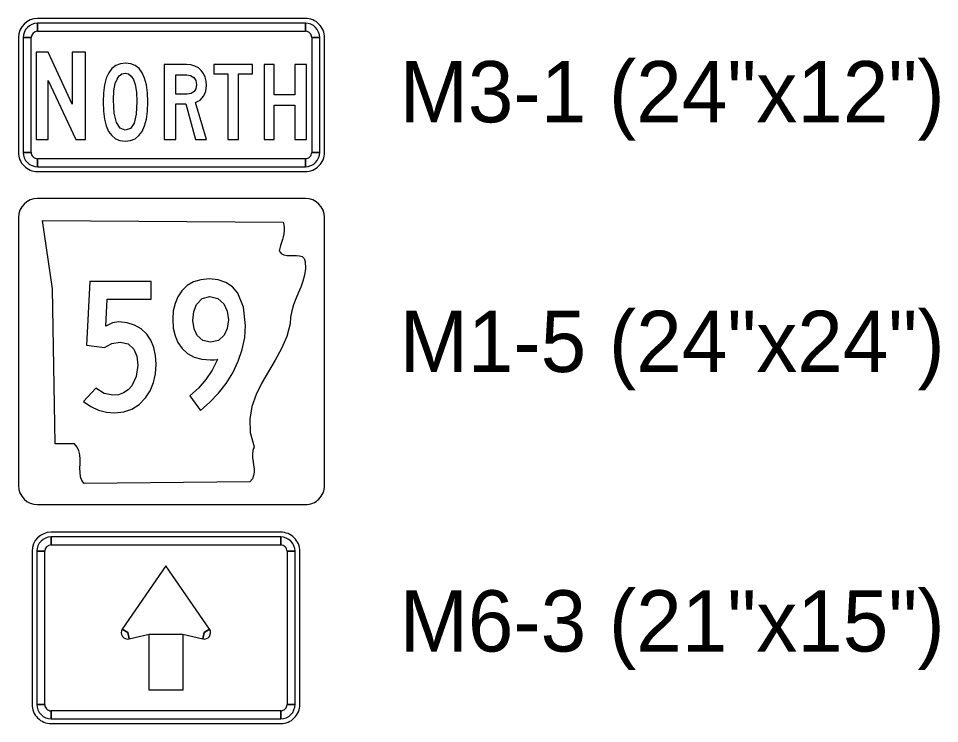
# Model space of a CAD drawing. Extents: x 620864 to 620948.6, y 415499.7 to 415559.1.
# Drawn here: x 620910.53 to 620916.55, y 415510.88 to 415515.48 of the extents above; entities that cross this region are included whole.
import ezdxf

# ---------------------------------------------------------------- set-up
doc = ezdxf.new("R2010")
doc.units = 0
doc.layers.add('SIGNS', color=7, linetype='Continuous')

msp = doc.modelspace()

# ---------------------------------------------------------------- linework, layer by layer
at = {"layer": 'SIGNS'}
for p, q in [((620912.4076, 415515.4826), (620910.6576, 415515.4826)), ((620910.6576, 415515.3993), (620910.6576, 415515.4514)), ((620912.4076, 415515.4514), (620912.4076, 415515.3993)), ((620910.5326, 415515.3576), (620910.5326, 415514.6076)), ((620910.5639, 415515.3576), (620910.616, 415515.3576)), ((620912.4493, 415515.3576), (620912.5014, 415515.3576)), ((620912.5326, 415514.6076), (620912.5326, 415515.3576)), ((620910.616, 415514.6076), (620910.5639, 415514.6076)), ((620912.5014, 415514.6076), (620912.4493, 415514.6076)), ((620910.6576, 415514.5139), (620910.6576, 415514.566)), ((620912.4076, 415514.566), (620912.4076, 415514.5139)), ((620910.6576, 415514.4826), (620912.4076, 415514.4826)), ((620912.4076, 415514.307), (620910.6576, 415514.307)), ((620910.5326, 415514.182), (620910.5326, 415512.432)), ((620912.5326, 415512.432), (620912.5326, 415514.182)), ((620910.5326, 415512.432), (620910.5326, 415512.432)), ((620910.6576, 415512.307), (620912.4076, 415512.307)), ((620912.2465, 415512.1272), (620910.7465, 415512.1272)), ((620910.7465, 415512.0438), (620910.7465, 415512.0959)), ((620912.2465, 415512.0959), (620912.2465, 415512.0438)), ((620910.6215, 415512.0022), (620910.6215, 415511.0022)), ((620910.6528, 415512.0022), (620910.7049, 415512.0022)), ((620912.2882, 415512.0022), (620912.3403, 415512.0022)), ((620912.3715, 415511.0022), (620912.3715, 415512.0022)), ((620911.2465, 415511.4709), (620911.2113, 415511.4932)), ((620911.2559, 415511.4303), (620911.2465, 415511.4709)), ((620911.7465, 415511.4709), (620911.7372, 415511.4303)), ((620911.7818, 415511.4932), (620911.7465, 415511.4709)), ((620910.7049, 415511.0022), (620910.6528, 415511.0022)), ((620912.3403, 415511.0022), (620912.2882, 415511.0022)), ((620910.7465, 415510.9084), (620910.7465, 415510.9605)), ((620912.2465, 415510.9605), (620912.2465, 415510.9084)), ((620910.7465, 415510.8772), (620912.2465, 415510.8772))]:
    msp.add_line(p, q, dxfattribs=at)
for points in [[(620912.4076, 415515.4514), (620910.6576, 415515.4514), (620910.6576, 415515.3993), (620912.4076, 415515.3993), (620912.4076, 415515.4514), (620912.4076, 415515.4514)], [(620910.5639, 415515.3576), (620910.5639, 415514.6076), (620910.616, 415514.6076), (620910.616, 415515.3576), (620910.5639, 415515.3576), (620910.5639, 415515.3576)], [(620912.5014, 415514.6076), (620912.5014, 415515.3576), (620912.4493, 415515.3576), (620912.4493, 415514.6076), (620912.5014, 415514.6076), (620912.5014, 415514.6076)], [(620910.648, 415514.691), (620910.7264, 415514.691), (620910.7264, 415515.0774), (620910.907, 415514.691), (620910.971, 415514.691), (620910.971, 415515.263), (620910.8835, 415515.263), (620910.8835, 415514.9217), (620910.7264, 415515.263), (620910.648, 415515.263)], [(620911.8998, 415514.691), (620911.971, 415514.691), (620911.971, 415515.1197), (620912.0625, 415515.1197), (620912.0625, 415515.1813), (620911.8103, 415515.1813), (620911.8103, 415515.1197), (620911.8998, 415515.1197)], [(620912.1373, 415514.691), (620912.2045, 415514.691), (620912.2045, 415514.916), (620912.3392, 415514.916), (620912.3392, 415514.691), (620912.4141, 415514.691), (620912.4141, 415515.1813), (620912.3392, 415515.1813), (620912.3392, 415514.9847), (620912.2045, 415514.9847), (620912.2045, 415515.1813), (620912.1373, 415515.1813)], [(620910.6576, 415514.5139), (620912.4076, 415514.5139), (620912.4076, 415514.566), (620910.6576, 415514.566), (620910.6576, 415514.5139), (620910.6576, 415514.5139)], [(620912.2625, 415514.1526), (620912.2672, 415514.1335), (620912.2689, 415514.1141), (620912.2682, 415514.0949), (620912.2659, 415514.0759), (620912.2619, 415514.0568), (620912.2572, 415514.0381), (620912.2515, 415514.019), (620912.2458, 415514.0006), (620912.2405, 415513.9823), (620912.2355, 415513.9639), (620912.2495, 415513.9477), (620912.2669, 415513.9386), (620912.2866, 415513.9345), (620912.308, 415513.9342), (620912.3293, 415513.9349), (620912.3501, 415513.9353), (620912.3691, 415513.9331), (620912.3858, 415513.9268), (620912.3989, 415513.9147), (620912.4069, 415513.8945), (620912.4076, 415513.849), (620912.4019, 415513.8064), (620912.3912, 415513.766), (620912.3768, 415513.7275), (620912.3611, 415513.6893), (620912.345, 415513.6515), (620912.33, 415513.6129), (620912.318, 415513.5733), (620912.3097, 415513.5318), (620912.3077, 415513.4878), (620912.2856, 415513.4055), (620912.2518, 415513.3273), (620912.211, 415513.2517), (620912.1669, 415513.1768), (620912.1238, 415513.1023), (620912.0861, 415513.0263), (620912.058, 415512.9477), (620912.0436, 415512.8651), (620912.047, 415512.7778), (620912.0727, 415512.6841), (620912.065, 415512.661), (620912.0624, 415512.6372), (620912.063, 415512.6133), (620912.066, 415512.5891), (620912.0694, 415512.5652), (620912.072, 415512.5417), (620912.0727, 415512.5186), (620912.0694, 415512.4969), (620912.061, 415512.4756), (620912.0456, 415512.4558), (620910.9619, 415512.4459), (620910.9472, 415512.4657), (620910.9389, 415512.4896), (620910.9352, 415512.516), (620910.9349, 415512.5443), (620910.9355, 415512.574), (620910.9359, 415512.6034), (620910.9339, 415512.6324), (620910.9282, 415512.6592), (620910.9171, 415512.6834), (620910.8988, 415512.704), (620910.7725, 415512.704), (620910.7544, 415513.7157), (620910.6909, 415514.1625), (620912.2625, 415514.1526), (620912.2625, 415514.1526)], [(620910.9575, 415512.981), (620911.0051, 415512.948), (620911.0551, 415512.9247), (620911.1073, 415512.9109), (620911.162, 415512.9063), (620911.2213, 415512.9122), (620911.2744, 415512.9304), (620911.3214, 415512.9609), (620911.3623, 415513.0039), (620911.393, 415513.0514), (620911.4149, 415513.104), (620911.4281, 415513.1615), (620911.4327, 415513.2245), (620911.4289, 415513.2819), (620911.4172, 415513.3341), (620911.3979, 415513.3802), (620911.3708, 415513.4207), (620911.3342, 415513.4553), (620911.2919, 415513.4802), (620911.2429, 415513.4952), (620911.1883, 415513.5003), (620911.147, 415513.4936), (620911.1034, 415513.4735), (620911.1126, 415513.6489), (620911.3997, 415513.6489), (620911.3997, 415513.7645), (620910.999, 415513.7645), (620910.9785, 415513.3485), (620911.0949, 415513.3335), (620911.1439, 415513.3595), (620911.1968, 415513.3683), (620911.2489, 415513.3565), (620911.2868, 415513.3217), (620911.3064, 415513.2757), (620911.3131, 415513.2187), (620911.303, 415513.144), (620911.2731, 415513.0828), (620911.2486, 415513.0558), (620911.2199, 415513.0369), (620911.1867, 415513.0253), (620911.1493, 415513.0217), (620911.092, 415513.0334), (620911.0382, 415513.0687)], [(620912.2465, 415512.0959), (620910.7465, 415512.0959), (620910.7465, 415512.0438), (620912.2465, 415512.0438), (620912.2465, 415512.0959), (620912.2465, 415512.0959)], [(620910.6528, 415512.0022), (620910.6528, 415511.0022), (620910.7049, 415511.0022), (620910.7049, 415512.0022), (620910.6528, 415512.0022), (620910.6528, 415512.0022)], [(620912.3403, 415511.0022), (620912.3403, 415512.0022), (620912.2882, 415512.0022), (620912.2882, 415511.0022), (620912.3403, 415511.0022), (620912.3403, 415511.0022)], [(620911.4965, 415511.9084), (620911.2113, 415511.4932), (620911.2465, 415511.4709), (620911.2559, 415511.4303), (620911.3872, 415511.4605), (620911.6059, 415511.4605), (620911.7372, 415511.4303), (620911.7465, 415511.4709), (620911.7818, 415511.4932), (620911.4965, 415511.9084), (620911.4965, 415511.9084)], [(620911.6059, 415511.0959), (620911.3872, 415511.0959), (620911.3872, 415511.4605), (620911.6059, 415511.4605), (620911.6059, 415511.0959), (620911.6059, 415511.0959)], [(620910.7465, 415510.9084), (620912.2465, 415510.9084), (620912.2465, 415510.9605), (620910.7465, 415510.9605), (620910.7465, 415510.9084), (620910.7465, 415510.9084)]]:
    msp.add_lwpolyline(points, close=True, dxfattribs=at)
for points in [[(620911.3779, 415514.9369), (620911.3754, 415514.9962), (620911.3687, 415515.0479), (620911.3574, 415515.0915), (620911.3417, 415515.1274), (620911.321, 415515.155), (620911.2963, 415515.175), (620911.2668, 415515.1869), (620911.233, 415515.191), (620911.1985, 415515.1869), (620911.1686, 415515.175), (620911.1433, 415515.155), (620911.1227, 415515.1274), (620911.1067, 415515.0915), (620911.0953, 415515.0479), (620911.0883, 415514.9962), (620911.0861, 415514.9369), (620911.0882, 415514.8768), (620911.095, 415514.8249), (620911.1062, 415514.7809), (620911.122, 415514.7452), (620911.1422, 415514.7171), (620911.1669, 415514.6972), (620911.1962, 415514.6853), (620911.23, 415514.6814), (620911.2646, 415514.6853), (620911.2946, 415514.6972), (620911.32, 415514.7171), (620911.3409, 415514.7452), (620911.357, 415514.7809), (620911.3685, 415514.8249), (620911.3754, 415514.8768), (620911.3779, 415514.9369)], [(620911.484, 415514.691), (620911.5609, 415514.691), (620911.5609, 415514.9244), (620911.6263, 415514.9244), (620911.6905, 415514.691), (620911.7608, 415514.691), (620911.6896, 415514.9327), (620911.72, 415514.9498), (620911.7431, 415514.9768), (620911.7563, 415515.0082), (620911.7608, 415515.044), (620911.7587, 415515.0735), (620911.7524, 415515.0999), (620911.742, 415515.123), (620911.7276, 415515.143), (620911.7086, 415515.1597), (620911.686, 415515.1717), (620911.66, 415515.1789), (620911.6307, 415515.1813), (620911.484, 415515.1813), (620911.484, 415514.691)], [(620911.3073, 415514.9391), (620911.3024, 415514.8574), (620911.288, 415514.7992), (620911.2641, 415514.7643), (620911.2308, 415514.7527), (620911.1968, 415514.765), (620911.1726, 415514.8023), (620911.1582, 415514.8643), (620911.1534, 415514.9515), (620911.1564, 415515.0093), (620911.1657, 415515.0574), (620911.1768, 415515.0868), (620911.1914, 415515.1081), (620911.2093, 415515.1208), (620911.2308, 415515.1251), (620911.2518, 415515.1205), (620911.2697, 415515.1065), (620911.2842, 415515.0832), (620911.2955, 415515.0509), (620911.3043, 415515), (620911.3073, 415514.9391)], [(620911.5609, 415514.989), (620911.5609, 415515.114), (620911.6328, 415515.114), (620911.658, 415515.1097), (620911.6782, 415515.097), (620911.6911, 415515.0771), (620911.6954, 415515.0512), (620911.6915, 415515.0238), (620911.6803, 415515.0045), (620911.6615, 415514.9928), (620911.6352, 415514.989), (620911.5609, 415514.989)], [(620910.6576, 415514.307), (620910.6576, 415514.307)], [(620912.4076, 415514.307), (620912.4076, 415514.307)], [(620910.5326, 415514.182), (620910.5326, 415514.182)], [(620911.653, 415513.0179), (620911.7219, 415512.9227), (620911.7843, 415512.9755), (620911.8403, 415513.0341), (620911.8898, 415513.098), (620911.9331, 415513.1677), (620911.9692, 415513.2441), (620911.9955, 415513.3212), (620912.0109, 415513.399), (620912.0164, 415513.4777), (620912.0038, 415513.5966), (620911.9664, 415513.6881), (620911.9315, 415513.7287), (620911.8888, 415513.7578), (620911.8376, 415513.7751), (620911.7789, 415513.781), (620911.7245, 415513.7761), (620911.6767, 415513.7617), (620911.6352, 415513.7375), (620911.6004, 415513.7036), (620911.5743, 415513.665), (620911.5558, 415513.621), (620911.5447, 415513.5718), (620911.5411, 415513.5174), (620911.5447, 415513.4601), (620911.5563, 415513.4093), (620911.5751, 415513.365), (620911.6022, 415513.3271), (620911.638, 415513.294), (620911.6809, 415513.2706), (620911.7307, 415513.2566), (620911.7874, 415513.252), (620911.8113, 415513.2536), (620911.8348, 415513.2554), (620911.8323, 415513.2554), (620911.7988, 415513.1862), (620911.7577, 415513.1239), (620911.709, 415513.0676), (620911.653, 415513.0179)], [(620911.9042, 415513.5143), (620911.8973, 415513.4576), (620911.8768, 415513.413), (620911.839, 415513.3794), (620911.7874, 415513.3683), (620911.7374, 415513.3789), (620911.7005, 415513.4112), (620911.6799, 415513.455), (620911.6731, 415513.5099), (620911.6788, 415513.5679), (620911.6963, 415513.6149), (620911.7324, 415513.6528), (620911.7833, 415513.6655), (620911.8348, 415513.6536), (620911.8743, 415513.6182), (620911.8967, 415513.5711), (620911.9042, 415513.5143)], [(620910.6576, 415512.307), (620910.6576, 415512.307)], [(620912.4076, 415512.307), (620912.4076, 415512.307)]]:
    msp.add_lwpolyline(points, dxfattribs=at)
for centre, radius, start, end in [((620910.6576, 415515.3576), 0.125, 90.00021, 179.99985), ((620910.6576, 415515.3576), 0.0937, 90.00021, 179.99985), ((620912.4076, 415515.3576), 0.125, 360, 90.00021), ((620912.4076, 415515.3576), 0.0937, 360, 90.00021), ((620910.6576, 415515.3576), 0.0417, 90.00021, 179.99985), ((620912.4076, 415515.3576), 0.0417, 360, 90.00021), ((620910.6576, 415514.6076), 0.125, 179.99985, 270.00006), ((620910.6576, 415514.6076), 0.0937, 179.99985, 270.00006), ((620910.6576, 415514.6076), 0.0417, 179.99985, 270.00006), ((620912.4076, 415514.6076), 0.125, 270.00006, 0.00027), ((620912.4076, 415514.6076), 0.0937, 270.00006, 0.00027), ((620912.4076, 415514.6076), 0.0417, 270.00006, 0.00027), ((620910.6576, 415514.182), 0.125, 90.00021, 179.99985), ((620912.4076, 415514.182), 0.125, 360, 90), ((620910.6576, 415512.432), 0.125, 180, 270), ((620912.4076, 415512.432), 0.125, 270.00006, 0.00027), ((620910.7465, 415512.0022), 0.125, 90.00021, 179.99985), ((620912.2465, 415512.0022), 0.125, 360, 90.00021), ((620910.7465, 415512.0022), 0.0937, 90.00021, 179.99985), ((620912.2465, 415512.0022), 0.0937, 360, 90.00021), ((620910.7465, 415512.0022), 0.0417, 90.00021, 179.99985), ((620912.2465, 415512.0022), 0.0417, 360, 90.00021), ((620911.2465, 415511.4709), 0.0417, 147.72456, 282.95062), ((620911.7465, 415511.4709), 0.0417, 257.04949, 32.27555), ((620910.7465, 415511.0022), 0.125, 179.99985, 270.00006), ((620910.7465, 415511.0022), 0.0937, 179.99985, 270.00006), ((620910.7465, 415511.0022), 0.0417, 179.99985, 270.00006), ((620912.2465, 415511.0022), 0.0937, 270.00006, 0.00027), ((620912.2465, 415511.0022), 0.0417, 270.00006, 0.00027), ((620912.2465, 415511.0022), 0.125, 270.00006, 0.00027)]:
    msp.add_arc(centre, radius, start, end, dxfattribs=at)

# ---------------------------------------------------------------- texts
for s, p in [('M3-1 (24"x12")', (620913.0237, 415514.804)), ('M1-5 (24"x24")', (620913.0237, 415513.1732)), ('M6-3 (21"x15")', (620913.0237, 415511.3476))]:
    msp.add_text(s, height=0.4, rotation=0, dxfattribs=at).set_placement(p)

doc.saveas('drawing.dxf')
